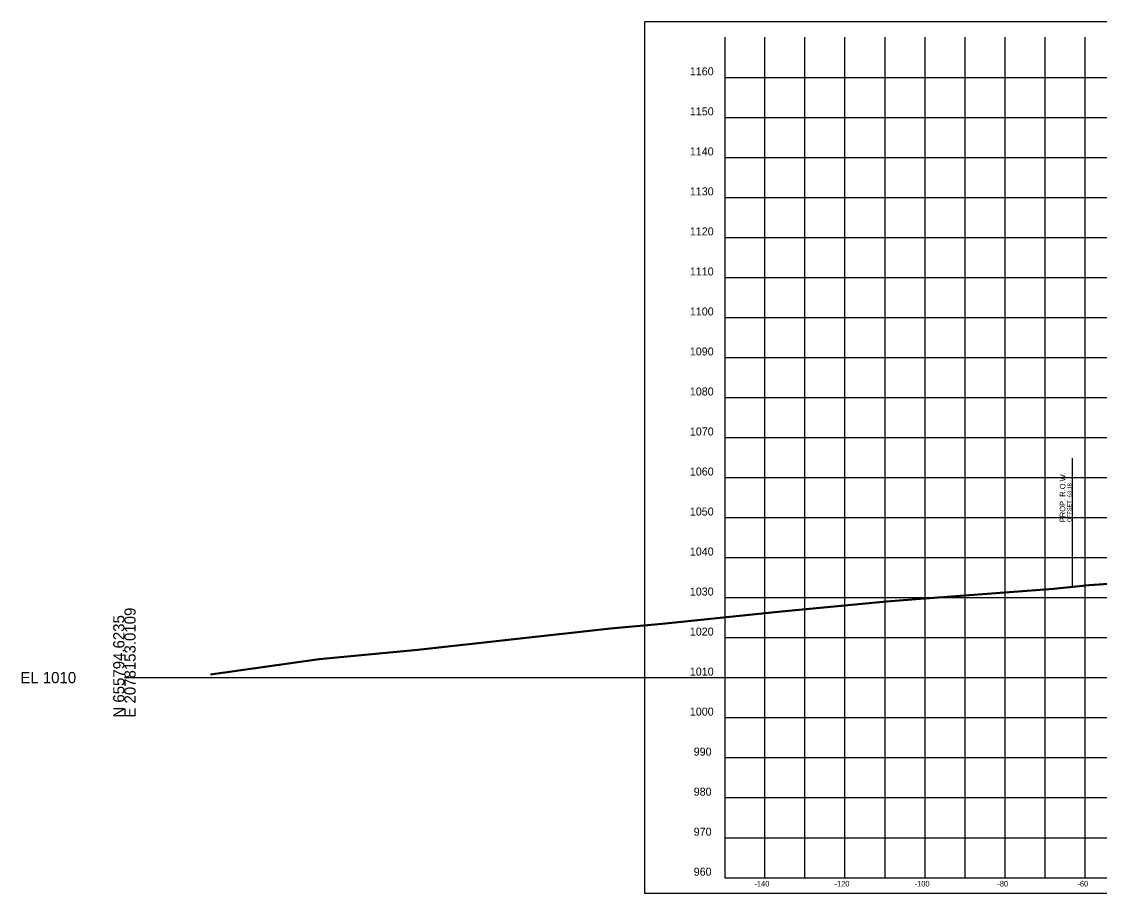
# Model space of a CAD drawing. Extents: x 5868 to 6683, y 2883 to 19120.
# Drawn here: x 5868.1 to 6137.3, y 8391.1 to 8609 of the extents above; entities that cross this region are included whole.
import ezdxf

# ---------------------------------------------------------------- set-up
doc = ezdxf.new("R2010")
doc.units = 0
for name, color, linetype in [('DESIGN - ROW - Right-of-Way and Easement Labels', 7, 'Continuous'), ('DESIGN - ROW - Right-of-Way Linework', 7, 'Continuous'), ('DESIGN - SHEET - Corner Text', 7, 'Continuous'), ('DESIGN - SHEET - Light Grid', 7, 'Continuous'), ('DESIGN - SHEET - Linework', 7, 'Continuous'), ('DESIGN - SHEET - Plot Shape', 7, 'Continuous'), ('SURVEY - GROUND - Bottom of Topsoil Layer', 7, 'Continuous'), ('SURVEY - GROUND - Top of Ground', 7, 'Continuous')]:
    doc.layers.add(name, color=color, linetype=linetype)

msp = doc.modelspace()

# ---------------------------------------------------------------- linework, layer by layer
at = {"layer": 'DESIGN - ROW - Right-of-Way Linework'}
msp.add_line((6130.6, 8467.91), (6130.6, 8499.91), dxfattribs=at)
at = {"layer": 'DESIGN - SHEET - Light Grid'}
msp.add_line((5893.78, 8445.07), (6193.78, 8445.07), dxfattribs=at)
at = {"layer": 'DESIGN - SHEET - Linework'}
for p, q in [((6053.78, 8395.07), (6053.78, 8605.07)), ((6063.78, 8395.07), (6063.78, 8605.07)), ((6073.78, 8395.07), (6073.78, 8605.07)), ((6083.78, 8395.07), (6083.78, 8605.07)), ((6093.78, 8395.07), (6093.78, 8605.07)), ((6103.78, 8395.07), (6103.78, 8605.07)), ((6113.78, 8395.07), (6113.78, 8605.07)), ((6123.78, 8395.07), (6123.78, 8605.07)), ((6133.78, 8395.07), (6133.78, 8605.07)), ((6043.78, 8595.07), (6343.78, 8595.07)), ((6043.78, 8585.07), (6343.78, 8585.07)), ((6043.78, 8575.07), (6343.78, 8575.07)), ((6043.78, 8565.07), (6343.78, 8565.07)), ((6043.78, 8555.07), (6343.78, 8555.07)), ((6043.78, 8545.07), (6343.78, 8545.07)), ((6043.78, 8535.07), (6343.78, 8535.07)), ((6043.78, 8525.07), (6343.78, 8525.07)), ((6043.78, 8515.07), (6343.78, 8515.07)), ((6043.78, 8505.07), (6343.78, 8505.07)), ((6043.78, 8495.07), (6343.78, 8495.07)), ((6043.78, 8485.07), (6343.78, 8485.07)), ((6043.78, 8475.07), (6343.78, 8475.07)), ((6043.78, 8465.07), (6343.78, 8465.07)), ((6043.78, 8455.07), (6343.78, 8455.07)), ((6043.78, 8445.07), (6343.78, 8445.07)), ((6043.78, 8435.07), (6343.78, 8435.07)), ((6043.78, 8425.07), (6343.78, 8425.07)), ((6043.78, 8415.07), (6343.78, 8415.07)), ((6043.78, 8405.07), (6343.78, 8405.07))]:
    msp.add_line(p, q, dxfattribs=at)
msp.add_lwpolyline([(6043.78, 8605.07), (6043.78, 8395.07), (6343.78, 8395.07), (6343.78, 8605.07)], dxfattribs=at)
at = {"layer": 'DESIGN - SHEET - Plot Shape'}
msp.add_lwpolyline([(6023.78, 8609.01), (6363.78, 8609.01), (6363.78, 8391.13), (6023.78, 8391.13)], close=True, dxfattribs=at)
at = {"layer": 'SURVEY - GROUND - Bottom of Topsoil Layer'}
for p, q in [((6134.77, 8468.1), (6161.13, 8469.9)), ((6092.66, 8464.69), (6125.89, 8467.15)), ((6125.89, 8467.15), (6134.77, 8468.1)), ((6057.12, 8461.45), (6084.15, 8464)), ((6084.15, 8464), (6092.66, 8464.69)), ((6028.12, 8458.42), (6057.12, 8461.45)), ((6015.23, 8457.28), (6028.12, 8458.42)), ((5967.12, 8451.93), (6015.23, 8457.28)), ((5915.25, 8445.77), (5942.47, 8449.62)), ((5942.47, 8449.62), (5967.12, 8451.93))]:
    msp.add_line(p, q, dxfattribs=at)
at = {"layer": 'SURVEY - GROUND - Top of Ground'}
msp.add_lwpolyline([(5915.25, 8446.02), (5942.47, 8449.87), (5967.12, 8452.18), (6015.23, 8457.53), (6028.12, 8458.67), (6057.12, 8461.7), (6084.15, 8464.25), (6092.66, 8464.94), (6125.89, 8467.4), (6134.77, 8468.35), (6161.13, 8470.15)], dxfattribs=at)

# ---------------------------------------------------------------- texts
at = {"layer": 'DESIGN - ROW - Right-of-Way and Easement Labels'}
for s, height, p in [('PROP. R.O.W.', 1.4, (6128.85, 8483.91)), ('OFFSET -63.18', 1, (6130.35, 8483.91))]:
    msp.add_text(s, height=height, rotation=90, dxfattribs=at).set_placement(p)
at = {"layer": 'DESIGN - SHEET - Corner Text'}
for s, height, p in [('1160', 2, (6035.03, 8595.57)), ('1150', 2, (6035.03, 8585.57)), ('1140', 2, (6035.03, 8575.57)), ('1130', 2, (6035.03, 8565.57)), ('1120', 2, (6035.03, 8555.57)), ('1110', 2, (6035.03, 8545.57)), ('1100', 2, (6035.03, 8535.57)), ('1090', 2, (6035.03, 8525.57)), ('1080', 2, (6035.03, 8515.57)), ('1070', 2, (6035.03, 8505.57)), ('1060', 2, (6035.03, 8495.57)), ('1050', 2, (6035.03, 8485.57)), ('1040', 2, (6035.03, 8475.57)), ('1030', 2, (6035.03, 8465.57)), ('1020', 2, (6035.03, 8455.57)), ('1010', 2, (6035.03, 8445.57)), ('1000', 2, (6035.03, 8435.57)), ('990', 2, (6036, 8425.57)), ('980', 2, (6036, 8415.57)), ('970', 2, (6036, 8405.57)), ('960', 2, (6036, 8395.57)), ('-140', 1.4, (6051.16, 8392.87)), ('-120', 1.4, (6071.16, 8392.87)), ('-100', 1.4, (6091.16, 8392.87)), ('-80', 1.4, (6111.84, 8392.87)), ('-60', 1.4, (6131.84, 8392.87))]:
    msp.add_text(s, height=height, dxfattribs=at).set_placement(p)
at = {"layer": 'DESIGN - SHEET - Light Grid'}
for s, p in [('N 655794.6235', (5893.78, 8435.07)), ('E 2078153.0109', (5896.58, 8435.07))]:
    msp.add_text(s, height=2.8, rotation=90, dxfattribs=at).set_placement(p)
msp.add_text('EL 1010', height=2.8, dxfattribs=at).set_placement((5867.78, 8443.67))

doc.saveas('drawing.dxf')
